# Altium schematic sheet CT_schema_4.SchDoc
size 208 x 258 mm
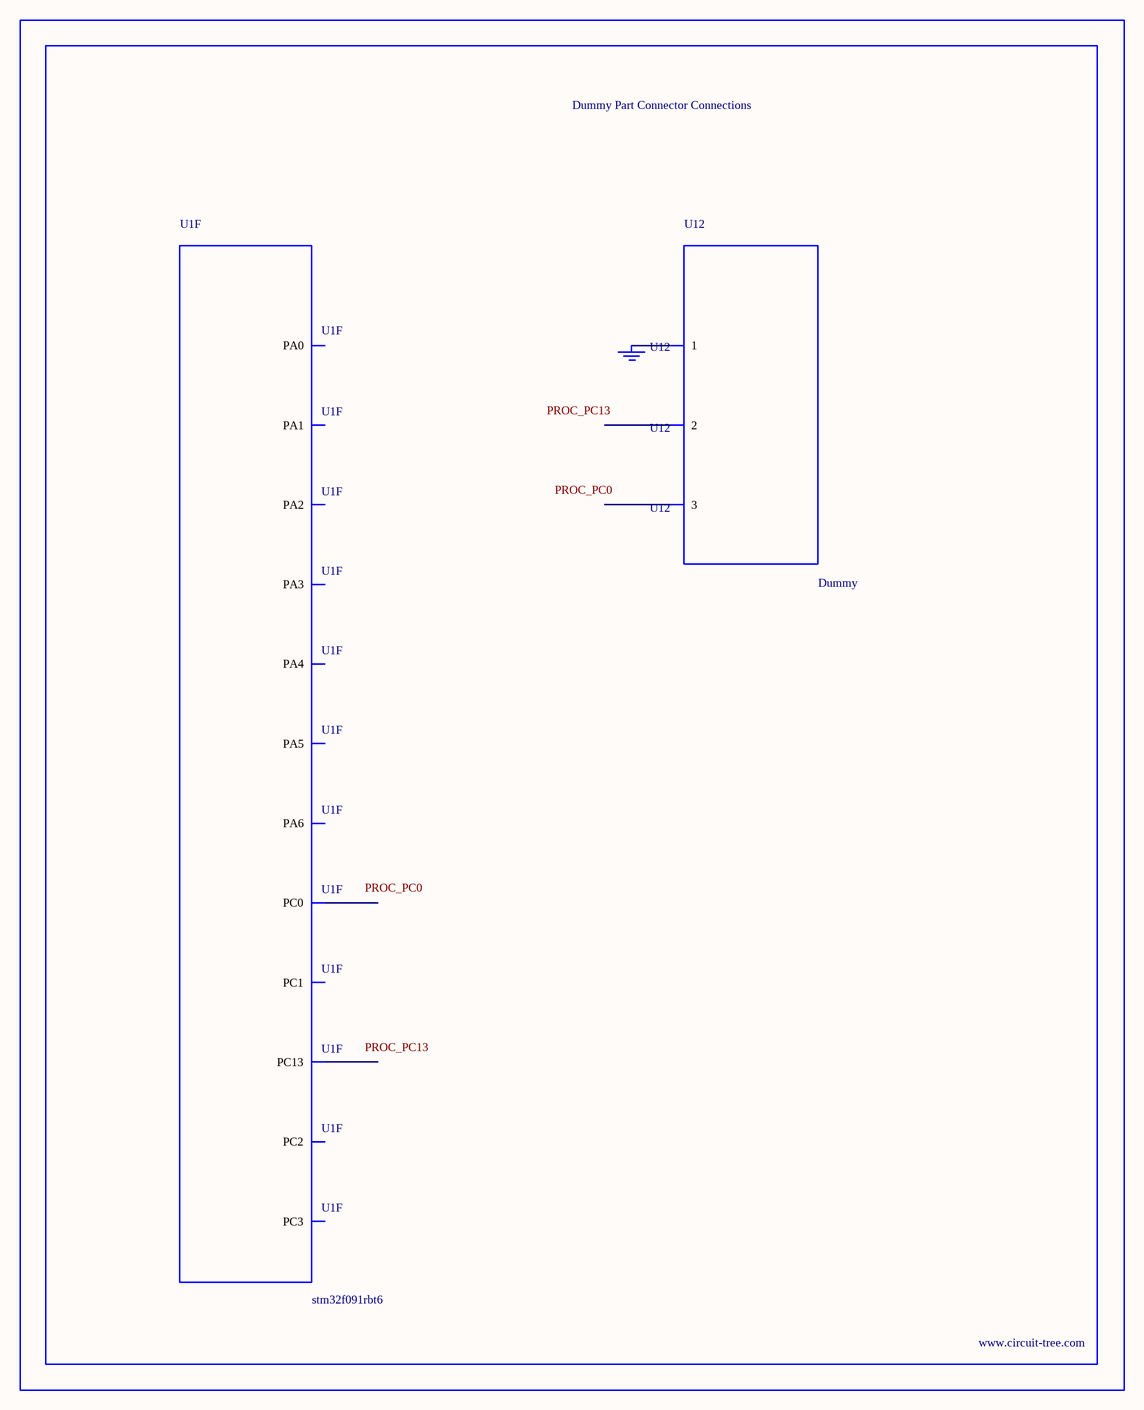
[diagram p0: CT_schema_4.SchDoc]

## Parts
BORDER3  (no value)
GND_INSTANCE_3_0  (no value)
U1  stm32f091rbt6  [LQFP64]  (part F of 6)
U12  Dummy  [DUMMY_PACKAGE_127]

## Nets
NetGND_INSTANCE_3_0_0: GND_INSTANCE_3_0.0(GND) U12.1

Not connected (* = marked no-connect by the designer): U1 2(PC13) 8(PC0) 9(PC1) 10(PC2) 11(PC3) 14(PA0) 15(PA1) 16(PA2) 17(PA3) 20(PA4) 21(PA5) 22(PA6); U12 2 3

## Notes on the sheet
- Labels drawn without touching a wire or pin: PROC_PC0, PROC_PC13

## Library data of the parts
BORDER3 = BORDER_PAGE3
GND_INSTANCE_3_0 = GND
